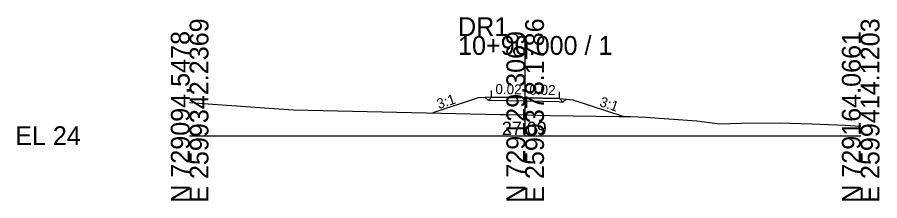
# Model space of a CAD drawing. Extents: x -26 to 1162, y -10 to 9515.
# Drawn here: x -25.7 to 102.8, y 4490.3 to 4517.7 of the extents above; entities that cross this region are included whole.
import ezdxf

# ---------------------------------------------------------------- set-up
doc = ezdxf.new("R2010")
doc.units = 0
for name, color, linetype in [('Exist Cross Section Cell', 7, 'Continuous'), ('Exist XS Center Line Elevation Label', 7, 'Continuous'), ('Exist XS Ground Line', 7, 'Continuous'), ('Prop XS Ditch Slope Text', 7, 'Continuous'), ('Prop XS Dump Level', 7, 'Continuous'), ('Prop XS EOT Tick Mark', 7, 'Continuous'), ('Prop XS Finish Grade', 7, 'Continuous'), ('Prop XS Finish Grade Earthwork', 7, 'Continuous'), ('Prop XS Finish Grade Pavement', 7, 'Continuous'), ('Prop XS Pvmt Edge Slope', 7, 'Continuous'), ('Prop XS SE Text', 7, 'Continuous'), ('Prop XS Subgrade Earthwork', 7, 'Continuous')]:
    doc.layers.add(name, color=color, linetype=linetype)

msp = doc.modelspace()

# ---------------------------------------------------------------- linework, layer by layer
at = {"layer": 'Exist Cross Section Cell'}
for p, q in [((50, 4500), (50, 4514.85)), ((0, 4500), (50, 4500)), ((50, 4500), (100, 4500))]:
    msp.add_line(p, q, dxfattribs=at)
at = {"layer": 'Exist XS Ground Line'}
msp.add_lwpolyline([(0, 4504.95), (11.85, 4504.1), (15.45, 4503.88), (46.25, 4503.16), (47.05, 4503.14), (50.02, 4503.09), (53.74, 4503.02), (63.98, 4502.85), (65.77, 4502.84), (67.91, 4502.76), (75.6, 4502.24), (79, 4501.79), (82.19, 4501.86), (87.9, 4501.9), (92.71, 4501.79), (97.71, 4501.58), (100, 4501.43)], dxfattribs=at)
at = {"layer": 'Prop XS Dump Level'}
for p, q in [((50, 4505.63), (45, 4505.73)), ((45, 4505.73), (50, 4505.63)), ((55.11, 4505.53), (50, 4505.63)), ((50, 4505.63), (55.11, 4505.53))]:
    msp.add_line(p, q, dxfattribs=at)
at = {"layer": 'Prop XS EOT Tick Mark'}
for p, q in [((45, 4505.73), (45, 4506.73)), ((55.11, 4505.53), (55.11, 4506.53))]:
    msp.add_line(p, q, dxfattribs=at)
at = {"layer": 'Prop XS Finish Grade'}
for p, q in [((45, 4505.73), (44.06, 4505.69)), ((55.11, 4505.53), (56.1, 4505.45))]:
    msp.add_line(p, q, dxfattribs=at)
at = {"layer": 'Prop XS Finish Grade Earthwork'}
for p, q in [((43, 4505.65), (36.24, 4503.4)), ((44.06, 4505.69), (43, 4505.65)), ((56.1, 4505.45), (57.12, 4505.37)), ((57.12, 4505.37), (64.69, 4502.85))]:
    msp.add_line(p, q, dxfattribs=at)
at = {"layer": 'Prop XS Finish Grade Pavement'}
for p, q in [((45, 4505.73), (50, 4505.63)), ((50, 4505.63), (55.11, 4505.53))]:
    msp.add_line(p, q, dxfattribs=at)
at = {"layer": 'Prop XS Pvmt Edge Slope'}
for p, q in [((44.06, 4505.69), (44.51, 4505.24)), ((45, 4505.73), (44.51, 4505.24)), ((55.11, 4505.53), (55.63, 4505.02)), ((56.1, 4505.45), (55.63, 4505.02))]:
    msp.add_line(p, q, dxfattribs=at)
at = {"layer": 'Prop XS Subgrade Earthwork'}
for p, q in [((44.51, 4505.24), (44.06, 4505.69)), ((44.51, 4505.24), (44.06, 4505.69)), ((45, 4505.23), (44.51, 4505.24)), ((50, 4505.13), (45, 4505.23)), ((55.11, 4505.03), (50, 4505.13)), ((55.63, 4505.02), (56.1, 4505.45)), ((55.63, 4505.02), (56.1, 4505.45)), ((55.11, 4505.03), (55.63, 4505.02))]:
    msp.add_line(p, q, dxfattribs=at)

# ---------------------------------------------------------------- texts
at = {"layer": 'Exist Cross Section Cell'}
for s, p in [('E 2599342.2369', (2.8, 4490)), ('E 2599378.1786', (52.8, 4490)), ('E 2599414.1203', (102.8, 4490)), ('N 729094.5478', (0, 4490)), ('N 729129.3069', (50, 4490)), ('N 729164.0661', (100, 4490))]:
    msp.add_text(s, height=2.8, rotation=90, dxfattribs=at).set_placement(p)
for s, p in [('DR1', (40, 4514.85)), ('10+90.000 / 1', (40, 4512.05)), ('EL 24', (-26, 4498.6))]:
    msp.add_text(s, height=2.8, dxfattribs=at).set_placement(p)
at = {"layer": 'Exist XS Center Line Elevation Label'}
msp.add_text('27.09', height=2, dxfattribs=at).set_placement((46.52, 4500.09))
at = {"layer": 'Prop XS Ditch Slope Text'}
for rotation, p in [(18.4349, (37.12, 4503.96)), (341.5883, (60.96, 4504.44))]:
    msp.add_text('3:1', height=1.5, rotation=rotation, dxfattribs=at).set_placement(p)
at = {"layer": 'Prop XS Dump Level'}
for p in [(43, 4505.61), (57.12, 4505.33)]:
    msp.add_text('Case1', height=0.04, dxfattribs=at).set_placement(p)
at = {"layer": 'Prop XS SE Text'}
for p in [(45.55, 4506.22), (50.61, 4506.12)]:
    msp.add_text('0.02', height=1.5, rotation=358.8542, dxfattribs=at).set_placement(p)

doc.saveas('drawing.dxf')
